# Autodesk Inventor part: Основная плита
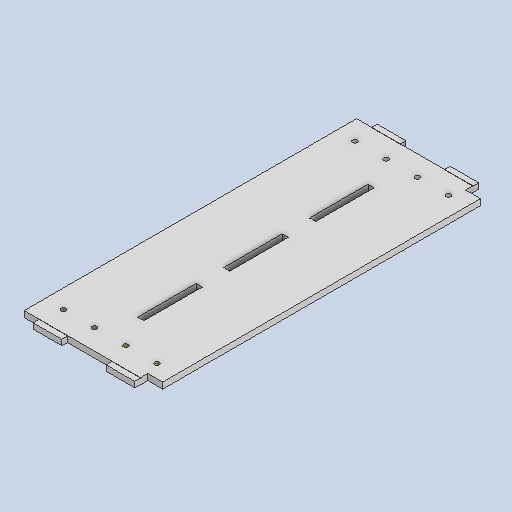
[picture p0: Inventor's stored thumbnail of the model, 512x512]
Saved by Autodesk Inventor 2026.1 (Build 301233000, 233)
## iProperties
Created: 2025-12
Part Number: Основная плита
Material: Типовые
Document SubType Name: Modeling
Designer: Yury Melnikov
Density: 1 g/cm^3
Appearance: Фанера — с эффектом атмосферных воздействий
Author: Yury Melnikov
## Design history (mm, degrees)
derived "Направляющие.ipt"
sketch "Эскиз1"
  geometry: L1 (47.09, -193)-(42.89, -193) reference; L2 (42.89, -193)-(42.89, -153) reference; L3 (42.89, -153)-(47.09, -153) reference; L4 (47.09, -153)-(47.09, -193) reference; L5 (47.09, -134)-(42.89, -134) reference; L6 (42.89, -134)-(42.89, -94) reference; L7 (42.89, -94)-(47.09, -94) reference; L8 (47.09, -94)-(47.09, -134) reference; L9 (47.09, -75)-(42.89, -75) reference; L10 (42.89, -75)-(42.89, -35) reference; L11 (42.89, -35)-(47.09, -35) reference; L12 (47.09, -35)-(47.09, -75) reference; L13 (79.78, 0)-(0, 0) reference; L14 (0, 0)-(0, -228) reference; L15 (79.78, -228)-(0, -228) reference; L16 (89.98, -5)-(89.98, -223) reference; L17 (0, 0)-(0, -228) reference; L18 (0, -114)-(89.98, -114); L19 (79.78, -223)-(89.98, -223) reference; L20 (89.98, -5)-(79.78, -5) reference; L21 (79.78, -5)-(79.78, 0) reference; L22 (79.78, -228)-(79.78, -223) reference; C1 r 1.65 at (55.686, -14) reference; C2 r 1.65 at (34.293, -14) reference; C3 r 1.65 at (77.08, -14) reference; C4 r 1.65 at (12.9, -14) reference; C5 r 1.65 at (55.686, -214); C6 r 1.65 at (34.293, -214); C7 r 1.65 at (77.08, -214); C8 r 1.65 at (12.9, -214); 1 further point
  constraints: 4 centre point, 4 symmetric about line, 2 end point, 2 midpoint, 4 other
extrude "Выдавливание1" cut sketch "Эскиз1" distance "d1" = 10; taper "d2" = 0 deg
feature "Основная плита::Направляющие.ipt" dims "d0" = 10
tag "Элемент создания тегов1"
node "Спроецированная петля1"
node "Основная плита"
